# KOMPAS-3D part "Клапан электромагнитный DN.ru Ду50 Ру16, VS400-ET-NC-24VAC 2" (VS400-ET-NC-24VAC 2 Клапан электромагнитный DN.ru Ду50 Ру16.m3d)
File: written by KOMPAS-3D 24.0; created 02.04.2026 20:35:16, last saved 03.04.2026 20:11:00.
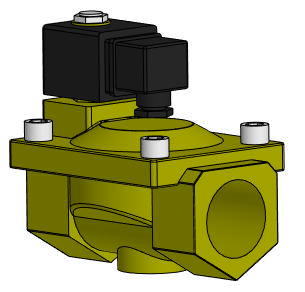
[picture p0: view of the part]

Document properties: Автор: artio; Полное имя файла: C:\Users\artio\OneDrive\Рабочий стол\Клапан электромагнитный DN.ru\VS400-ET-NC\VS400-ET-NC-24VAC 2 Клапан электромагнитный DN.ru Ду50 Ру16.m3d

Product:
- Body: Тело 1  | qty 1
    Масса: 7.119215
- Part/product: Клапан электромагнитный DN.ru Ду50 Ру16  | designation VS400-ET-NC-24VAC 2
    Масса: 3.509
    Раздел спецификации: Прочие изделия
    Примечание: D130-05492
    additional columns: ef56311e-7521-43dc-8291-0e6108b3d81d; VS400-ET-NC-220VAC 2; artio; c; Шероховатость не задана; Да

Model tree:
1. Операция без истории:1

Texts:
  VS400-ET-NC-24VAC 2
